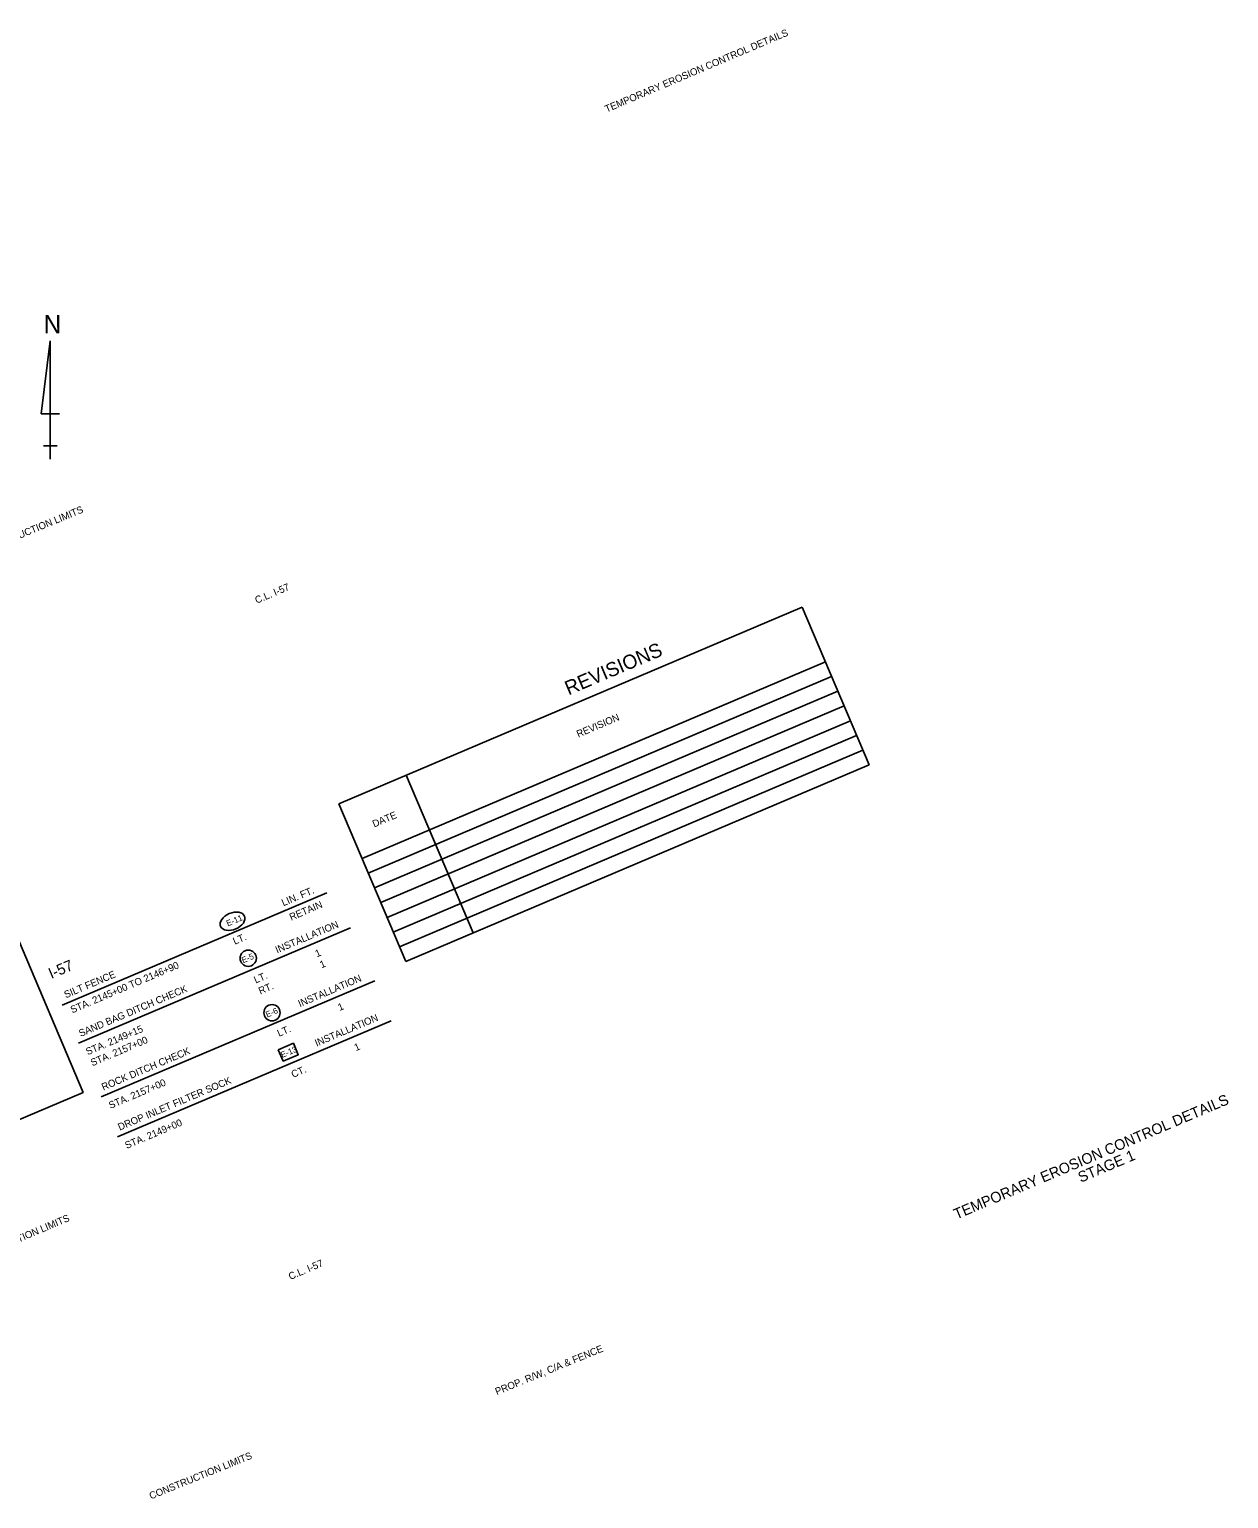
# Model space of a CAD drawing. Extents: x 1718855 to 1720684, y 766616 to 767857.
# Drawn here: x 1719671 to 1720684, y 766616 to 767857 of the extents above; entities that cross this region are included whole.
import ezdxf

# ---------------------------------------------------------------- set-up
doc = ezdxf.new("R2010")
doc.units = 0
for name, color, linetype in [('1', 7, 'Continuous'), ('44', 7, 'Continuous'), ('63', 7, 'Continuous'), ('Default', 7, 'Continuous'), ('G-ANNO-TEXT', 7, 'Continuous'), ('Level 44', 7, 'Continuous'), ('R_Draft', 7, 'Continuous')]:
    doc.layers.add(name, color=color, linetype=linetype)

msp = doc.modelspace()

# ---------------------------------------------------------------- linework, layer by layer
at = {"layer": '1'}
for points in [[(1719293.7, 766940.4), (1719658.9, 767095.4), (1719716.6, 766959.2), (1719351.5, 766804.3)], [(1719881.4, 766995.2), (1719894.3, 767000.7), (1719898.4, 766991), (1719885.5, 766985.6)]]:
    msp.add_lwpolyline(points, close=True, dxfattribs=at)
for centre in [(1719856.1, 767072.5), (1719876.2, 767026.5)]:
    msp.add_circle(centre, 6.88, dxfattribs=at)
msp.add_ellipse((1719842.9, 767103.7), major_axis=(10.1, 4.3), ratio=0.638788, dxfattribs=at)
at = {"layer": '44'}
for p, q in [((1719699.1, 767032.9), (1719922.4, 767127.6)), ((1719712.8, 767000.7), (1719942.5, 767098.2)), ((1719732, 766955.4), (1719963.1, 767053.5)), ((1719745.8, 766921.6), (1719976.8, 767019.6))]:
    msp.add_line(p, q, dxfattribs=at)
at = {"layer": '63'}
for p, q in [((1719688.9, 767593.7), (1719681.2, 767532.2)), ((1719688.9, 767493.7), (1719688.9, 767593.7)), ((1719688.9, 767593.7), (1719688.9, 767516.8)), ((1719681.2, 767532.2), (1719696.6, 767532.2)), ((1719688.9, 767493.7), (1719688.9, 767516.8)), ((1719688.9, 767505.2), (1719683.1, 767505.2)), ((1719683.1, 767505.2), (1719694.7, 767505.2)), ((1719688.9, 767493.7), (1719688.9, 767505.2))]:
    msp.add_line(p, q, dxfattribs=at)
at = {"layer": 'Default'}
for p, q in [((1719932.7, 767202.8), (1720324, 767368.8)), ((1720324, 767368.8), (1720380.4, 767235.7)), ((1719952.3, 767156.8), (1720343.5, 767322.7)), ((1719957.5, 767144.3), (1720348.8, 767310.3)), ((1719962.8, 767131.9), (1720354.1, 767297.9)), ((1719968.1, 767119.5), (1720359.3, 767285.5)), ((1719968.1, 767119.5), (1720359.3, 767285.5)), ((1719973.4, 767107), (1720364.6, 767273)), ((1719978.6, 767094.6), (1720369.9, 767260.6)), ((1719983.9, 767082.2), (1720375.1, 767248.2)), ((1719989.2, 767069.8), (1720380.4, 767235.7)), ((1719989.6, 767226.9), (1720046.1, 767093.9)), ((1719932.7, 767202.8), (1719989.2, 767069.8))]:
    msp.add_line(p, q, dxfattribs=at)

# ---------------------------------------------------------------- texts
at = {"layer": '1'}
for s, rotation, p in [('E-11', 22.9899, (1719838.9, 767099.3)), ('E-5 ', 22.9899, (1719851.8, 767068.2)), ('E-6 ', 22.9899, (1719872.1, 767022.3)), ('E-13', 22.6076, (1719884.8, 766988.3))]:
    msp.add_text(s, height=5, rotation=rotation, dxfattribs=at).set_placement(p)
at = {"layer": '44'}
for s, p in [('LIN. FT.', (1719885.8, 767116.3)), ('RETAIN', (1719892.4, 767104.1)), ('INSTALLATION', (1719880.5, 767076.5)), ('LT.', (1719844.7, 767083.8)), ('1', (1719914.1, 767073.2)), ('STA. 2145+00 TO 2146+90', (1719707.5, 767025.9)), ('1', (1719918, 767063.9)), ('SILT FENCE      ', (1719702.1, 767038.6)), ('LT.', (1719862.4, 767051.1)), ('INSTALLATION', (1719899.8, 767031.1)), ('SAND BAG DITCH CHECK', (1719714.6, 767006)), ('RT.', (1719866.3, 767041.8)), ('1', (1719933.3, 767027.9)), ('STA. 2149+15', (1719720.5, 766990.5)), ('LT.', (1719882.1, 767006.1)), ('INSTALLATION', (1719913.9, 766997.8)), ('STA. 2157+00', (1719724.5, 766981.2)), ('ROCK DITCH CHECK', (1719733.8, 766960.7)), ('1', (1719947.1, 766994)), ('CT.', (1719894, 766971.4)), ('STA. 2157+00', (1719739.8, 766945.2)), ('DROP INLET FILTER SOCK', (1719747.6, 766926.9)), ('STA. 2149+00', (1719753.5, 766911.4))]:
    msp.add_text(s, height=6, rotation=22.9899, dxfattribs=at).set_placement(p)
at = {"layer": '63'}
msp.add_text('N', height=15.4, rotation=360, dxfattribs=at).set_placement((1719683.3, 767600.1))
at = {"layer": 'Default'}
for s, height, p in [('REVISIONS', 12, (1720126.6, 767294.3)), ('REVISION', 6, (1720134.9, 767258.7)), ('DATE', 6, (1719962.5, 767182.8))]:
    msp.add_text(s, height=height, rotation=22.9899, dxfattribs=at).set_placement(p)
at = {"layer": 'G-ANNO-TEXT'}
for s, height, p in [('TEMPORARY EROSION CONTROL DETAILS', 6, (1720158.8, 767786.4)), ('TEMPORARY EROSION CONTROL DETAILS', 9, (1720454.2, 766851.8)), ('STAGE 1', 9, (1720559.2, 766882.9))]:
    msp.add_text(s, height=height, rotation=22.9899, dxfattribs=at).set_placement(p)
at = {"layer": 'Level 44'}
msp.add_text('I-57', height=9.14, rotation=22.9899, dxfattribs=at).set_placement((1719689.8, 767054.9))
at = {"layer": 'R_Draft'}
for s, rotation, p in [('CONSTRUCTION LIMITS', 22.5, (1719631.8, 767413.6)), ('C.L. I-57', 23, (1719863.3, 767371.7)), ('CONSTRUCTION LIMITS', 23, (1719620.5, 766814.7)), ('C.L. I-57', 23, (1719891.7, 766800.8)), ('PROP. R/W, C/A & FENCE', 22.2954, (1720066.1, 766703.6)), ('CONSTRUCTION LIMITS', 22.0356, (1719774, 766615.5))]:
    msp.add_text(s, height=6, rotation=rotation, dxfattribs=at).set_placement(p)

doc.saveas('drawing.dxf')
